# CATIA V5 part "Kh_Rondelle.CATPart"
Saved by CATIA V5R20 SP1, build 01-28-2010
Part number: Rondelle
Bounding box of the stored display mesh (mm): x 0 to 2.5, y -13.5 to 13.5, z -13.49 to 13.49
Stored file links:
  G:\Khaled_CFAO_2011\SIL\SIL_GR1\tmerino\Khaled\CAD_Thinkmotion\Kh_Rondelle.CATPart
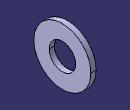
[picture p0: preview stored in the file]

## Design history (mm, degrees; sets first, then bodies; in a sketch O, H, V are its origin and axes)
Body1 (main body)
  Sketch1 on yz-plane, origin (0, 0, 0), H (0, 1, 0), V (0, 0, 1)
    circle A1 centre (0, 0) radius 6.25
    circle A2 centre (0, 0) radius 13.5
    radius A2 = 13.5
    radius A1 = 6.25
  Pad1: profile Sketch1, direction (1, 0, 0), length 2.5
